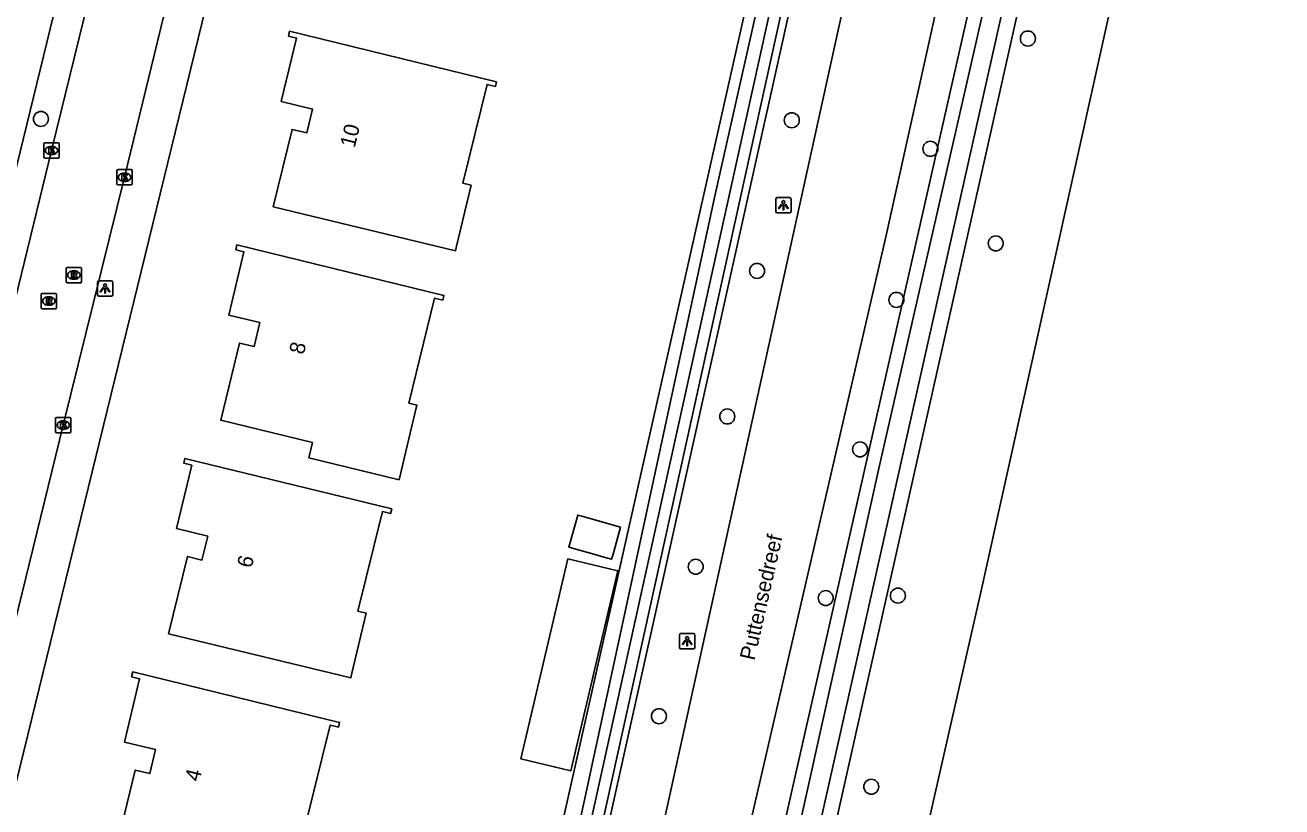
# Model space of a CAD drawing. Extents: x 163268 to 164360, y 381529 to 382285.
# Drawn here: x 164107.1 to 164189.1, y 382073.8 to 382124.8 of the extents above; entities that cross this region are included whole.
import ezdxf

# ---------------------------------------------------------------- set-up
doc = ezdxf.new("R2010")
doc.units = 0
for name, color, linetype in [('IMGEO_Boom', 7, 'Continuous'), ('IMGEO_Gemengd_bos', 7, 'Continuous'), ('IMGEO_Groenvoorziening', 7, 'Continuous'), ('IMGEO_Haag', 7, 'Continuous'), ('IMGEO_Hek', 7, 'Continuous'), ('IMGEO_Kolk', 7, 'Continuous'), ('IMGEO_Lichtpunt', 7, 'Continuous'), ('IMGEO_Openbare_ruimte_label', 7, 'Continuous'), ('IMGEO_Pand', 7, 'Continuous'), ('IMGEO_Pand_nummerreeks', 7, 'Continuous'), ('IMGEO_Rijbaan_lokaal_gesloten', 7, 'Continuous'), ('IMGEO_Rijbaan_lokaal_open', 7, 'Continuous'), ('IMGEO_Rioolput', 7, 'Continuous'), ('IMGEO_Voetpad_open', 7, 'Continuous'), ('IMGEO_Waterloop', 7, 'Continuous')]:
    doc.layers.add(name, color=color, linetype=linetype)

msp = doc.modelspace()

# ---------------------------------------------------------------- linework, layer by layer
at = {"layer": 'IMGEO_Boom'}
for centre in [(164172.564, 382123.906), (164108.165, 382118.658), (164157.161, 382118.574), (164166.204, 382116.709), (164170.47, 382110.536), (164154.893, 382108.741), (164163.986, 382106.85), (164152.954, 382099.238), (164161.616, 382097.093), (164150.889, 382089.431), (164159.373, 382087.387), (164164.083, 382087.544), (164148.493, 382079.674), (164162.346, 382075.073)]:
    msp.add_circle(centre, 0.489, dxfattribs=at)
at = {"layer": 'IMGEO_Gemengd_bos'}
msp.add_lwpolyline([(164143.279, 381905.933), (164077.256, 381951.167), (164080.827, 381954.421), (164084.09, 381957.395), (164099.139, 381970.079), (164134.223, 382000), (164147.955, 382011.662), (164151.333, 382014.806), (164152.631, 382016.227), (164153.21, 382017.427), (164159.013, 382041.61), (164169.547, 382087.975), (164189.14, 382176.35)], dxfattribs=at)
at = {"layer": 'IMGEO_Groenvoorziening'}
for points in [[(164181.156, 382171.056), (164182.023, 382170.778), (164168.927, 382112.378), (164153.139, 382041.967), (164150.336, 382029.47), (164148.036, 382019.209), (164143.882, 382015.495), (164139.534, 382011.626), (164124.599, 381998.968), (164119.39, 381994.553), (164100.232, 381978.315), (164089.655, 381969.35), (164073.901, 381955.997), (164072.57, 381954.591), (164072.021, 381955.239)], [(164145.156, 382021.848), (164145.336, 382022.555), (164145.515, 382023.339), (164176.186, 382158.841), (164179.124, 382171.708), (164181.156, 382171.056)], [(164163.251, 382163.045), (164165.212, 382162.647), (164142.027, 382058.344), (164139.437, 382045.789)]]:
    msp.add_lwpolyline(points, dxfattribs=at)
at = {"layer": 'IMGEO_Haag'}
for points in [[(164105.277, 382054.312), (164136.378, 382046.624), (164137.69, 382046.3), (164140.278, 382058.679), (164152.15, 382113.717), (164163.251, 382163.045)], [(164158.4, 382147.143), (164158.546, 382145.474), (164136.554, 382047.613), (164115.328, 382052.943), (164101.851, 382056.216)]]:
    msp.add_lwpolyline(points, dxfattribs=at)
at = {"layer": 'IMGEO_Hek'}
msp.add_lwpolyline([(164143.279, 381905.933), (164077.256, 381951.167), (164080.827, 381954.421), (164084.09, 381957.395), (164099.139, 381970.079), (164134.223, 382000), (164147.955, 382011.662), (164151.333, 382014.806), (164152.631, 382016.227), (164153.21, 382017.427), (164159.013, 382041.61), (164169.547, 382087.975), (164189.14, 382176.35)], dxfattribs=at)
at = {"layer": 'IMGEO_Kolk'}
for p, q in [((164108.359, 382116.174), (164108.359, 382117.026)), ((164108.434, 382117.1), (164109.286, 382117.1)), ((164108.847, 382116.88), (164108.872, 382116.88)), ((164109.36, 382117.026), (164109.36, 382116.174)), ((164109.286, 382116.1), (164108.434, 382116.1)), ((164108.87, 382116.32), (164108.845, 382116.32)), ((164113.121, 382114.424), (164113.121, 382115.276)), ((164113.196, 382115.35), (164114.048, 382115.35)), ((164114.122, 382115.276), (164114.122, 382114.424)), ((164113.632, 382114.57), (164113.607, 382114.57)), ((164113.609, 382115.13), (164113.634, 382115.13)), ((164114.048, 382114.35), (164113.196, 382114.35)), ((164109.124, 382098.248), (164109.124, 382099.1)), ((164109.199, 382099.174), (164110.051, 382099.174)), ((164109.612, 382098.954), (164109.637, 382098.954)), ((164110.125, 382099.1), (164110.125, 382098.248)), ((164110.051, 382098.174), (164109.199, 382098.174)), ((164109.635, 382098.394), (164109.61, 382098.394))]:
    msp.add_line(p, q, dxfattribs=at)
for points in [[(164108.359, 382116.174), (164108.359, 382117.026)], [(164108.434, 382117.1), (164109.286, 382117.1)], [(164109.36, 382117.026), (164109.36, 382116.174)], [(164109.286, 382116.1), (164108.434, 382116.1)], [(164108.68, 382116.8), (164108.803, 382116.8), (164108.803, 382116.649), (164108.933, 382116.8), (164109.097, 382116.8), (164108.951, 382116.649), (164109.104, 382116.4), (164108.952, 382116.4), (164108.867, 382116.564), (164108.803, 382116.497), (164108.803, 382116.4), (164108.68, 382116.4), (164108.68, 382116.8)], [(164113.121, 382114.424), (164113.121, 382115.276)], [(164113.196, 382115.35), (164114.048, 382115.35)], [(164114.122, 382115.276), (164114.122, 382114.424)], [(164113.442, 382115.05), (164113.565, 382115.05), (164113.565, 382114.899), (164113.695, 382115.05), (164113.859, 382115.05), (164113.713, 382114.899), (164113.866, 382114.65), (164113.714, 382114.65), (164113.629, 382114.814), (164113.565, 382114.747), (164113.565, 382114.65), (164113.442, 382114.65), (164113.442, 382115.05)], [(164114.048, 382114.35), (164113.196, 382114.35)], [(164109.124, 382098.248), (164109.124, 382099.1)], [(164109.199, 382099.174), (164110.051, 382099.174)], [(164109.445, 382098.874), (164109.568, 382098.874), (164109.568, 382098.723), (164109.698, 382098.874), (164109.862, 382098.874), (164109.716, 382098.723), (164109.869, 382098.474), (164109.717, 382098.474), (164109.632, 382098.638), (164109.568, 382098.571), (164109.568, 382098.474), (164109.445, 382098.474), (164109.445, 382098.874)], [(164110.125, 382099.1), (164110.125, 382098.248)], [(164110.051, 382098.174), (164109.199, 382098.174)]]:
    msp.add_lwpolyline(points, dxfattribs=at)
for centre, start, end in [((164108.436, 382117.024), 91.55205, 178.44795), ((164108.436, 382117.024), 91.55205, 178.44795), ((164109.284, 382117.024), 1.55205, 88.44795), ((164109.284, 382117.024), 1.55205, 88.44795), ((164108.436, 382116.176), 181.55205, 268.44795), ((164108.436, 382116.176), 181.55205, 268.44795), ((164109.284, 382116.176), 271.55205, 358.44795), ((164109.284, 382116.176), 271.55205, 358.44795), ((164113.198, 382115.274), 91.55205, 178.44795), ((164113.198, 382115.274), 91.55205, 178.44795), ((164114.046, 382115.274), 1.55205, 88.44795), ((164114.046, 382115.274), 1.55205, 88.44795), ((164113.198, 382114.426), 181.55205, 268.44795), ((164113.198, 382114.426), 181.55205, 268.44795), ((164114.046, 382114.426), 271.55205, 358.44795), ((164114.046, 382114.426), 271.55205, 358.44795), ((164109.201, 382099.098), 91.55205, 178.44795), ((164109.201, 382099.098), 91.55205, 178.44795), ((164110.049, 382099.098), 1.55205, 88.44795), ((164110.049, 382099.098), 1.55205, 88.44795), ((164109.201, 382098.25), 181.55205, 268.44795), ((164109.201, 382098.25), 181.55205, 268.44795), ((164110.049, 382098.25), 271.55205, 358.44795), ((164110.049, 382098.25), 271.55205, 358.44795)]:
    msp.add_arc(centre, 0.0765, start, end, dxfattribs=at)
for centre, major_axis, ratio, start_param, end_param in [((164108.846, 382116.6), (-0.387, 0.002), 0.722429, 4.712389, 7.853982), ((164108.871, 382116.6), (-0.39, 0.002), 0.717154, 1.570796, 4.712389), ((164113.608, 382114.85), (-0.387, 0.002), 0.722429, 4.712389, 7.853982), ((164113.633, 382114.85), (-0.39, 0.002), 0.717154, 1.570796, 4.712389), ((164109.611, 382098.674), (-0.387, 0.002), 0.722429, 4.712389, 7.853982), ((164109.636, 382098.674), (-0.39, 0.002), 0.717154, 1.570796, 4.712389)]:
    msp.add_ellipse(centre, major_axis=major_axis, ratio=ratio, start_param=start_param, end_param=end_param, dxfattribs=at)
at = {"layer": 'IMGEO_Lichtpunt'}
for p, q in [((164156.117, 382113.431), (164156.117, 382112.624)), ((164156.117, 382113.431), (164156.117, 382112.624)), ((164157.019, 382113.526), (164156.211, 382113.526)), ((164157.019, 382113.526), (164156.211, 382113.526)), ((164157.113, 382112.624), (164157.113, 382113.431)), ((164157.113, 382112.624), (164157.113, 382113.431)), ((164156.211, 382112.53), (164157.019, 382112.53)), ((164156.211, 382112.53), (164157.019, 382112.53)), ((164111.853, 382107.994), (164111.853, 382107.187)), ((164111.853, 382107.994), (164111.853, 382107.187)), ((164112.755, 382108.089), (164111.947, 382108.089)), ((164112.755, 382108.089), (164111.947, 382108.089)), ((164112.849, 382107.187), (164112.849, 382107.994)), ((164112.849, 382107.187), (164112.849, 382107.994)), ((164111.947, 382107.093), (164112.755, 382107.093)), ((164111.947, 382107.093), (164112.755, 382107.093)), ((164149.836, 382084.976), (164149.836, 382084.169)), ((164149.836, 382084.976), (164149.836, 382084.169)), ((164150.738, 382085.071), (164149.93, 382085.071)), ((164150.738, 382085.071), (164149.93, 382085.071)), ((164150.832, 382084.169), (164150.832, 382084.976)), ((164150.832, 382084.169), (164150.832, 382084.976)), ((164149.93, 382084.075), (164150.738, 382084.075)), ((164149.93, 382084.075), (164150.738, 382084.075))]:
    msp.add_line(p, q, dxfattribs=at)
for points in [[(164156.491, 382113.095), (164156.53, 382113.067), (164156.342, 382112.805), (164156.304, 382112.832), (164156.491, 382113.095)], [(164156.593, 382113.047), (164156.64, 382113.047), (164156.64, 382112.725), (164156.593, 382112.725), (164156.593, 382113.047)], [(164156.703, 382113.067), (164156.741, 382113.094), (164156.928, 382112.832), (164156.889, 382112.804), (164156.703, 382113.067)], [(164112.227, 382107.658), (164112.266, 382107.63), (164112.078, 382107.368), (164112.04, 382107.395), (164112.227, 382107.658)], [(164112.329, 382107.61), (164112.376, 382107.61), (164112.376, 382107.288), (164112.329, 382107.288), (164112.329, 382107.61)], [(164112.439, 382107.63), (164112.477, 382107.657), (164112.664, 382107.395), (164112.625, 382107.367), (164112.439, 382107.63)], [(164150.21, 382084.64), (164150.249, 382084.612), (164150.061, 382084.35), (164150.023, 382084.377), (164150.21, 382084.64)], [(164150.312, 382084.592), (164150.359, 382084.592), (164150.359, 382084.27), (164150.312, 382084.27), (164150.312, 382084.592)], [(164150.422, 382084.612), (164150.46, 382084.639), (164150.647, 382084.377), (164150.608, 382084.349), (164150.422, 382084.612)]]:
    msp.add_lwpolyline(points, dxfattribs=at)
for centre in [(164156.616, 382113.229), (164112.352, 382107.792), (164150.335, 382084.774)]:
    msp.add_circle(centre, 0.0994, dxfattribs=at)
for centre, start, end in [((164156.211, 382113.431), 90, 180), ((164156.211, 382113.431), 90, 180), ((164157.019, 382113.431), 0, 90), ((164157.019, 382113.431), 0, 90), ((164156.211, 382112.624), 180, 270), ((164156.211, 382112.624), 180, 270), ((164157.019, 382112.624), 270, 0), ((164157.019, 382112.624), 270, 360), ((164111.947, 382107.994), 90, 180), ((164111.947, 382107.994), 90, 180), ((164112.755, 382107.994), 0, 90), ((164112.755, 382107.994), 0, 90), ((164111.947, 382107.187), 180, 270), ((164111.947, 382107.187), 180, 270), ((164112.755, 382107.187), 270, 0), ((164112.755, 382107.187), 270, 360), ((164149.93, 382084.976), 90, 180), ((164149.93, 382084.976), 90, 180), ((164150.738, 382084.976), 0, 90), ((164150.738, 382084.976), 0, 90), ((164149.93, 382084.169), 180, 270), ((164149.93, 382084.169), 180, 270), ((164150.738, 382084.169), 270, 0), ((164150.738, 382084.169), 270, 360)]:
    msp.add_arc(centre, 0.0946, start, end, dxfattribs=at)
at = {"layer": 'IMGEO_Pand'}
for points in [[(164137.891, 382121.088), (164137.816, 382120.778), (164137.274, 382120.91), (164135.701, 382114.456), (164136.232, 382114.329), (164135.285, 382110.357), (164135.213, 382110.055), (164123.328, 382112.932), (164124.554, 382117.975), (164125.506, 382117.743), (164125.89, 382119.307), (164123.849, 382119.799), (164124.846, 382123.932), (164124.322, 382124.069), (164124.391, 382124.377), (164137.891, 382121.088)], [(164125.891, 382097.536), (164125.648, 382096.535), (164131.537, 382095.11), (164131.851, 382096.413), (164132.703, 382099.987), (164132.173, 382100.113), (164133.847, 382106.964), (164134.381, 382106.834), (164134.457, 382107.144), (164120.957, 382110.433), (164120.888, 382110.125), (164121.412, 382109.988), (164120.415, 382105.855), (164122.456, 382105.363), (164122.072, 382103.799), (164121.12, 382104.031), (164119.894, 382098.988), (164125.891, 382097.536)], [(164128.45, 382082.482), (164129.387, 382086.411), (164128.85, 382086.539), (164130.448, 382093.034), (164130.98, 382092.903), (164131.056, 382093.213), (164117.556, 382096.502), (164117.487, 382096.194), (164118.011, 382096.057), (164117.014, 382091.924), (164119.055, 382091.432), (164118.671, 382089.868), (164117.719, 382090.1), (164116.493, 382085.057), (164128.378, 382082.18), (164128.45, 382082.482)], [(164145.989, 382092.02), (164143.459, 382092.727), (164143.195, 382092.801), (164142.609, 382090.703), (164144.549, 382090.16), (164144.746, 382090.104), (164145.402, 382089.921), (164145.496, 382090.258), (164145.989, 382092.02)], [(164142.548, 382089.948), (164139.474, 382076.898), (164142.747, 382076.12), (164145.809, 382089.171), (164142.548, 382089.948)], [(164124.398, 382068.38), (164125.437, 382072.592), (164127.042, 382079.095), (164127.575, 382078.964), (164127.651, 382079.274), (164114.151, 382082.563), (164114.082, 382082.255), (164114.606, 382082.118), (164113.609, 382077.985), (164115.65, 382077.493), (164115.266, 382075.929), (164114.314, 382076.161), (164113.088, 382071.118), (164124.398, 382068.38)]]:
    msp.add_lwpolyline(points, dxfattribs=at)
at = {"layer": 'IMGEO_Rijbaan_lokaal_gesloten'}
for points in [[(164144.535, 382029.718), (164163.296, 382110.969), (164171.818, 382149.402), (164175.019, 382162.921), (164175.285, 382164.128)], [(164167.311, 382156.884), (164143.201, 382047.269), (164142.926, 382046.066)]]:
    msp.add_lwpolyline(points, dxfattribs=at)
at = {"layer": 'IMGEO_Rijbaan_lokaal_open'}
for points in [[(164118.513, 382156.108), (164118.361, 382155.476), (164113.962, 382137.44), (164108.861, 382116.6), (164104.706, 382099.598), (164095.434, 382061.701), (164094.976, 382059.799)], [(164099.812, 382058.645), (164099.892, 382058.963), (164104.725, 382078.741), (164109.623, 382098.674), (164113.621, 382114.85), (164118.872, 382136.535), (164123.394, 382154.913)]]:
    msp.add_lwpolyline(points, dxfattribs=at)
at = {"layer": 'IMGEO_Rioolput'}
for p, q in [((164109.816, 382108.045), (164109.816, 382108.897)), ((164109.891, 382108.971), (164110.743, 382108.971)), ((164110.304, 382108.751), (164110.329, 382108.751)), ((164110.817, 382108.897), (164110.817, 382108.045)), ((164110.743, 382107.971), (164109.891, 382107.971)), ((164110.327, 382108.191), (164110.302, 382108.191)), ((164108.18, 382106.348), (164108.18, 382107.2)), ((164108.255, 382107.274), (164109.107, 382107.274)), ((164108.668, 382107.054), (164108.693, 382107.054)), ((164109.181, 382107.2), (164109.181, 382106.348)), ((164109.107, 382106.274), (164108.255, 382106.274)), ((164108.691, 382106.494), (164108.666, 382106.494))]:
    msp.add_line(p, q, dxfattribs=at)
for points in [[(164109.816, 382108.045), (164109.816, 382108.897)], [(164109.891, 382108.971), (164110.743, 382108.971)], [(164110.817, 382108.897), (164110.817, 382108.045)], [(164110.743, 382107.971), (164109.891, 382107.971)], [(164110.405, 382108.669), (164110.153, 382108.671), (164110.153, 382108.271)], [(164110.153, 382108.271), (164110.277, 382108.271), (164110.277, 382108.433), (164110.288, 382108.433)], [(164110.331, 382108.59), (164110.277, 382108.59), (164110.277, 382108.509)], [(164110.277, 382108.509), (164110.329, 382108.509)], [(164110.335, 382108.404), (164110.406, 382108.271), (164110.546, 382108.271), (164110.481, 382108.397)], [(164108.18, 382106.348), (164108.18, 382107.2)], [(164108.255, 382107.274), (164109.107, 382107.274)], [(164109.181, 382107.2), (164109.181, 382106.348)], [(164109.107, 382106.274), (164108.255, 382106.274)], [(164108.769, 382106.972), (164108.517, 382106.974), (164108.517, 382106.574)], [(164108.517, 382106.574), (164108.641, 382106.574), (164108.641, 382106.736), (164108.652, 382106.736)], [(164108.695, 382106.893), (164108.641, 382106.893), (164108.641, 382106.812)], [(164108.641, 382106.812), (164108.693, 382106.812)], [(164108.699, 382106.707), (164108.77, 382106.574), (164108.91, 382106.574), (164108.845, 382106.7)]]:
    msp.add_lwpolyline(points, dxfattribs=at)
for centre, radius, start, end in [((164109.893, 382108.895), 0.0765, 91.55205, 178.44795), ((164109.893, 382108.895), 0.0765, 91.55205, 178.44795), ((164110.741, 382108.895), 0.0765, 1.55205, 88.44795), ((164110.741, 382108.895), 0.0765, 1.55205, 88.44795), ((164109.893, 382108.047), 0.0765, 181.55205, 268.44795), ((164109.893, 382108.047), 0.0765, 181.55205, 268.44795), ((164110.287, 382108.38), 0.0533, 26.02933, 88.69889), ((164110.313, 382108.698), 0.19, 274.7715, 282.96867), ((164110.337, 382108.494), 0.0964, 77.00612, 93.18647), ((164110.351, 382108.551), 0.0378, 276.66336, 79.67722), ((164110.404, 382108.559), 0.109, 350.36119, 89.41601), ((164110.402, 382108.559), 0.112, 277.58423, 350.98172), ((164110.386, 382108.344), 0.108, 29.51342, 73.79051), ((164110.741, 382108.047), 0.0765, 271.55205, 358.44795), ((164110.741, 382108.047), 0.0765, 271.55205, 358.44795), ((164108.257, 382107.198), 0.0765, 91.55205, 178.44795), ((164108.257, 382107.198), 0.0765, 91.55205, 178.44795), ((164109.105, 382107.198), 0.0765, 1.55205, 88.44795), ((164109.105, 382107.198), 0.0765, 1.55205, 88.44795), ((164108.257, 382106.35), 0.0765, 181.55205, 268.44795), ((164108.257, 382106.35), 0.0765, 181.55205, 268.44795), ((164108.651, 382106.683), 0.0533, 26.02933, 88.69889), ((164108.677, 382107.001), 0.19, 274.7715, 282.96867), ((164108.701, 382106.797), 0.0964, 77.00612, 93.18647), ((164108.715, 382106.854), 0.0378, 276.66336, 79.67722), ((164108.768, 382106.862), 0.109, 350.36119, 89.41601), ((164108.766, 382106.862), 0.112, 277.58423, 350.98172), ((164108.75, 382106.647), 0.108, 29.51342, 73.79051), ((164109.105, 382106.35), 0.0765, 271.55205, 358.44795), ((164109.105, 382106.35), 0.0765, 271.55205, 358.44795)]:
    msp.add_arc(centre, radius, start, end, dxfattribs=at)
for centre, major_axis, ratio, start_param, end_param in [((164110.303, 382108.471), (-0.387, 0.002), 0.722429, 4.712389, 7.853982), ((164110.328, 382108.471), (-0.39, 0.002), 0.717154, 1.570796, 4.712389), ((164108.667, 382106.774), (-0.387, 0.002), 0.722429, 4.712389, 7.853982), ((164108.692, 382106.774), (-0.39, 0.002), 0.717154, 1.570796, 4.712389)]:
    msp.add_ellipse(centre, major_axis=major_axis, ratio=ratio, start_param=start_param, end_param=end_param, dxfattribs=at)
at = {"layer": 'IMGEO_Voetpad_open'}
for points in [[(164093.368, 382061.569), (164093.403, 382061.663), (164116.66, 382156.928)], [(164126.001, 382154.986), (164119.402, 382127.933), (164101.851, 382056.216)]]:
    msp.add_lwpolyline(points, dxfattribs=at)
at = {"layer": 'IMGEO_Waterloop'}
for points in [[(164180.847, 382170.105), (164179.856, 382170.423), (164162.876, 382096.049), (164154.383, 382057.745), (164146.308, 382022.32)], [(164144.27, 382018.897), (164082.879, 381967.006), (164071.506, 381957.392), (164072.611, 381956.089), (164073.212, 381956.724), (164139.316, 382012.753), (164147.13, 382019.741), (164180.847, 382170.105)], [(164138.844, 382045.712), (164164.52, 382162.063), (164163.84, 382162.212), (164162.248, 382155.227), (164138.031, 382045.542), (164137.784, 382045.599), (164104.918, 382053.636)]]:
    msp.add_lwpolyline(points, dxfattribs=at)

# ---------------------------------------------------------------- texts
at = {"layer": 'IMGEO_Openbare_ruimte_label'}
msp.add_text('Puttensedreef', height=1, rotation=77.22876, dxfattribs=at).set_placement((164154.726, 382083.27))
at = {"layer": 'IMGEO_Pand_nummerreeks'}
for s, p in [('10', (164128.636, 382116.732)), ('8', (164125.311, 382103.236)), ('6', (164121.909, 382089.301)), ('4', (164118.504, 382075.362))]:
    msp.add_text(s, height=1, rotation=76.20536, dxfattribs=at).set_placement(p)

doc.saveas('drawing.dxf')
